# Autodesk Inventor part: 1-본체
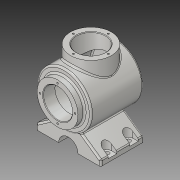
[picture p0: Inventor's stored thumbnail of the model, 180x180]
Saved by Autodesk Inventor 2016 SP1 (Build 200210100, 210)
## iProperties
Created: 2017-04
Part Number: 1-본체
Material: 알루미늄 6061
Document SubType Name: Modeling
Designer: H
Mass: 1664.52 g
Surface Area: 1066.88 cm^2
Volume: 616.49 cm^3
Density: 2.7 g/cm^3
Appearance: 알루미늄 - 평지
Author: H
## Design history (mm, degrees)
sketch "스케치1"
  geometry: L1 (0, 50)-(50, 50); L2 (50, 50)-(50, -46.336); L3 (50, -46.336)-(0, -46.336); L4 (0, -46.336)-(0, 50); L5 (0, 50)-(38, 50); L6 (38, 50)-(38, 62); L7 (38, 62)-(0, 62); L8 (0, 62)-(0, 50); L9 (0, -46.336)-(0, -58); A1 r 113 centre (0, 55) between (50, -46.336) and (0, -58); 1 further point
  constraints: 18 end point, 4 parallel, 2 horizontal, 2 perpendicular, 2 point on circle, 2 point on line, 1 centre point, 1 vertical
  dimensions: "d0" = 108 distance edge to line of A1 L1; "d1" = 100 diameter of L2 L4; "d2" = 12 distance of L5.end L6.end; "d3" = 76 diameter of L6 L4; "d5" = 113 radius of A1; "d6" = 50 distance from line of L1 point (0, 0)
revolve "회전1" sketch "스케치1" stored, may be unused: angle "d7" = 90 deg
sketch "스케치2"
  geometry: C1 r 38 at (0, 0); 1 further point
  constraints: 1 centre point, 1 coincident
  dimensions: "d9" = 76 diameter of C1
extrude "돌출1" join sketch "스케치2" distance "d10" = 65; taper "d11" = 0 deg
sketch "스케치4"
  geometry: L1 (-60, -82)-(60, -82); L2 (60, -82)-(60, -72); L3 (60, -72)-(-60, -72); L4 (-60, -72)-(-60, -82); L5 (-60, -72)-(-21.584, -45.101); L6 (60, -72)-(21.584, -45.101); C1 r 18 at (0, -82); A1 r 50 centre (0, 0) between (-21.584, -45.101) and (21.584, -45.101) reference; 3 further points
  constraints: 12 end point, 2 midpoint, 2 parallel, 2 point on circle, 1 centre point, 1 coincident, 1 equal length, 1 horizontal, 1 perpendicular, 1 vertical alignment
  dimensions: "d33" = 120 distance of L2.end L3.end; "d34" = 10 distance of L1.end L2.end; "d35" = 82 distance from line of point (0, 0) L1; "d36" = 55 deg angle of L5 L4; "d38" = 18 radius of C1
extrude "돌출2" join sketch "스케치4" distance "d39" = 42; taper "d40" = 0 deg; dims "d90" = 38, "d91" = 0
extrude "돌출3" cut sketch "스케치4" stored distance "d41" = 80; taper "d42" = 0 deg
sketch "스케치3"
  geometry: L1 (50, 50)-(50, -46.336) reference; L2 (-50, 50)-(50, 50) reference; L3 (-50, 50)-(-50, -46.336) reference; L4 (40, -39.916)-(40, 40); L5 (40, 40)-(-40, 40); L6 (-40, 40)-(-40, -39.916); L7 (0, 40)-(0, -48); A1 r 113 centre (0, 55) between (-50, -46.336) and (50, -46.336) reference; A2 r 103 centre (0, 55) between (-40, -39.916) and (40, -39.916); 1 further point
  constraints: 8 end point, 3 point on circle, 1 centre point, 1 midpoint, 1 parallel, 1 vertical, 1 other
  dimensions: "d12" = 10 radial gap between concentric circles of A1 A2; "d13" = 10 distance between parallel lines of L1 L4
revolve "회전2" sketch "스케치3" stored, may be unused: angle "d14" = 90 deg
fillet "모깎기1" dims "d8" = 3
hole "구멍1" diameter "d17" = 54; stored, may be unused: countersink angle "d21" = 90 deg, drill point angle "d23" = 118 deg; dims "d15" = 10, "d16" = 10, "d18" = 6, "d19" = 4, "d20" = 2, "d22" = 8
hole "구멍2" diameter "d26" = 54; stored, may be unused: countersink angle "d30" = 90 deg, drill point angle "d32" = 118 deg; dims "d24" = 10, "d25" = 10, "d27" = 6, "d28" = 4, "d29" = 2, "d31" = 8
sketch "스케치5"
  geometry: 2 further points
  constraints: 1 vertical alignment
  dimensions: "d44" = 32.5 distance of point (0, 32.5) point (0, 0)
hole "구멍3" sketch "스케치5" at (0, 32.5) diameter "d45" = 3.242; stored, may be unused: countersink angle "d49" = 90 deg, drill point angle "d51" = 118 deg; dims "d46" = 8, "d47" = 4, "d48" = 2, "d50" = 10
sketch "스케치6"
  geometry: 2 further points
  constraints: 1 vertical alignment
  dimensions: "d55" = 32.5 distance of point (0, 32.5) point (0, 0)
hole "구멍4" sketch "스케치6" at (0, 32.5) diameter "d56" = 3.242; stored, may be unused: countersink angle "d60" = 90 deg, drill point angle "d62" = 118 deg; dims "d57" = 8, "d58" = 4, "d59" = 2, "d61" = 10
chamfer "모따기1" distance "d66" = 1; stored, may be unused: second distance "d67" = 2, angle "d68" = 45 deg
fillet "모깎기2" dims "d69" = 3
fillet "모깎기3" dims "d70" = 3
node "작업 평면2"
sketch "스케치7"
  geometry: 2 further points
  constraints: 1 coincident, 1 other
feature "엠보싱1" sketch "스케치7" dims "d0" = 108, "d1" = 100, "d2" = 12, "d3" = 76, "d5" = 113, "d6" = 50, "d71" = 0.5, "d72" = 0
node "작업 평면1"
sketch "스케치8"
  geometry: L1 (-110, 58)-(-10, 58); L2 (-10, 58)-(-10, 18); L3 (-10, 18)-(-110, 18); L4 (-110, 18)-(-110, 58); L5 (-110, 58)-(-10, 18); L6 (-10, 58)-(-110, 18); L7 (-10, 26)-(0, 26); L8 (0, 26)-(0, 10); L9 (0, 10)-(-10, 10); L10 (-10, 10)-(-10, 26); L11 (0, 77)-(0, 3) reference; 2 further points
  constraints: 20 end point, 4 parallel, 3 midpoint, 2 horizontal, 2 perpendicular, 1 coincident, 1 collinear, 1 vertical alignment, 2 other
  dimensions: "d73" = 100 distance of L2.end L3.end; "d74" = 40 distance of L3.end L1.start; "d77" = 16 distance between parallel lines of L7 L9
extrude "돌출4" cut sketch "스케치8" stored distance "d75" = 80; taper "d76" = 0 deg
hole "구멍5" diameter "d83" = 8; stored, may be unused: countersink angle "d87" = 90 deg, drill point angle "d89" = 118 deg; dims "d81" = 10, "d82" = 10, "d84" = 8, "d85" = 4, "d86" = 2, "d88" = 10
node "솔리드1"
pattern_circular "원형 패턴1" dims angle "d53" = 360 deg
pattern_circular "원형 패턴2" dims angle "d64" = 360 deg
pattern_linear "직사각형 패턴1"
mirror "대칭1"
other parameters: "d43" = -6
